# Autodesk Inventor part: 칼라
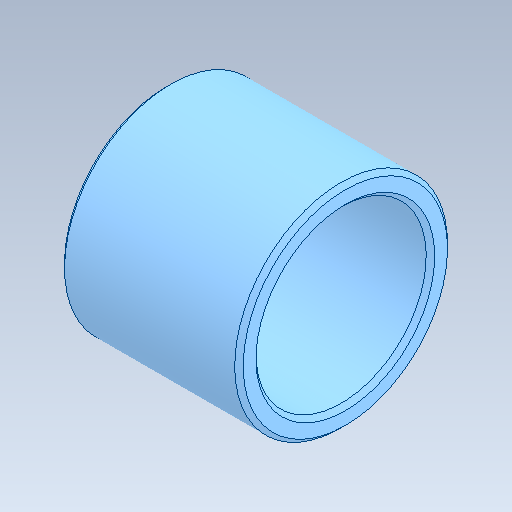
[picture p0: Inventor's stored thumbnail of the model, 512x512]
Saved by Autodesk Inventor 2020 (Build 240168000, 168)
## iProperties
Created: 2024-08
Part Number: 칼라
Material: 강철, 연강
Document SubType Name: Modeling
Designer: oem
Density: 7.85 g/cm^3
Appearance: 기본값
Author: jhkim
Sending System: Autodesk Inventor 2025
Preprocessor: ST-DEVELOPER v20
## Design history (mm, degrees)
node "칼라1"
node "솔리드2"
node "솔리드1"
